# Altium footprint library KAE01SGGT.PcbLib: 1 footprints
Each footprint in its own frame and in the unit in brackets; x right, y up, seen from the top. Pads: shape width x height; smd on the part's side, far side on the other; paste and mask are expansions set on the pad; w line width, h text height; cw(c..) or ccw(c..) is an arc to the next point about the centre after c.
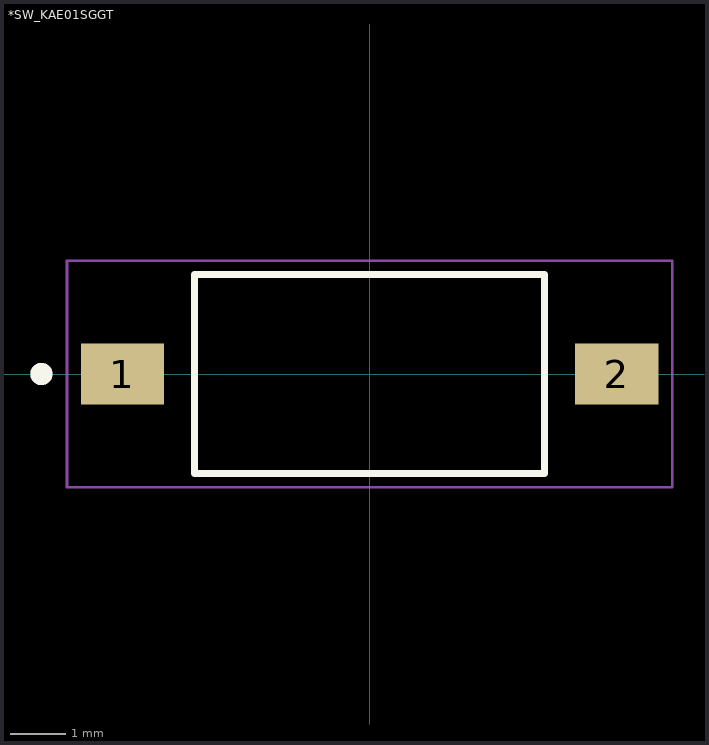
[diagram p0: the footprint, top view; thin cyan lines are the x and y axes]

## *SW_KAE01SGGT [mm]
pads (2):
  rect 1.5x1.1 smd: 1(-4.45,0) 2(4.45,0)
Top Overlay:
  circle w0.2: c-5.91,0 r0.1
  lines w0.127: -3.15,-1.79 -3.15,1.79 3.15,1.79 3.15,-1.79 -3.15,-1.79
Mechanical 4:
  circle w0.2: c-5.91,0 r0.1
  circle w0.2: c-5.91,0 r0.1
  lines w0.127: -3.15,-1.79 -3.15,1.79 ; -3.15,-1.79 3.15,-1.79 ; -3.15,-1.79 -3.15,1.79 ; -3.15,-1.79 3.15,-1.79 ; -3.15,1.79 3.15,1.79 ; -3.15,1.79 3.15,1.79 ; 3.15,-1.79 3.15,1.79 ; 3.15,-1.79 3.15,1.79
Mechanical 16:
  lines w0.05: -5.45,-2.04 -5.45,2.04 5.45,2.04 5.45,-2.04 -5.45,-2.04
